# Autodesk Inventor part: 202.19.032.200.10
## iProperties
Created: 2012-10
Part Number: 202.19.032.200.10
Catalog Web Link: www.cadenas.de
Description: 202.19. - Guide Pillar DIN 9825/ISO 9182-2
Document SubType Name: Modeling
Designer: PARTsolutions
Category: PARTsolutions
Title: 202.19.032.200.10
Author: Cadenas PARTsolutions
Comments: Guide Pillar DIN 9825/ISO 9182-2
NB: 202.19.032.200.10
NN: 202.19.
NT: Guide Pillar DIN 9825/ISO 9182-2
NBSYN: 202.19.0$D1..$L1..$TOL.
LINA: 202.19.032.200.10
ROWDESC: 202.19.032.200.10
DOC: 202_19_pdf
D1: 32.000
L1: 200.000
L2: 6.000
L4: 3.000
TOL: 10
R1: 5.000
FORM: B
TOLINHALT: '10','gelb','20','gruen','30','rot'
GEW: 1.262
KT: DUMMY
SUPPLIER: FIBRO
ARTICLENO: 202.19.032.200.10
BOMINFO: 202.19.032.200.10
CREATOR: CADENAS GmbH
PSOL_IDENT_0: {\\10.0.0.251\data_v9\23d-libs\fibro\normalien\d\d01\d01_01\202-19.prj},184 {VTYP=3D},{NB=202.19.032
PSOL_IDENT_1: .200.10},{LINA=202.19.032.200.10},{NN=202.19.},{DATE=10.05.2012 07:32:45},{GEOMDATE=15.11.2011 09:02
PSOL_IDENT_2: :00},{VERSION=v1},{LINEID=1430},{LINESUBID=-1},{WBVAR=TOL}  {NB=202.19.032.200.10},{LINA=202.19.032.
PSOL_IDENT_3: 200.10},{KT=DUMMY},{DOC=202_19_pdf},{D1=32.000},{L1=200.000},{L2=6.000},{L4=3.000},{TOL=10},{R1=5.00
PSOL_IDENT_4: 0},{FORM=B},{TOLINHALT='10','gelb','20','gruen','30','rot'},{GEW=1.262029}
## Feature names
1. Revolution1
